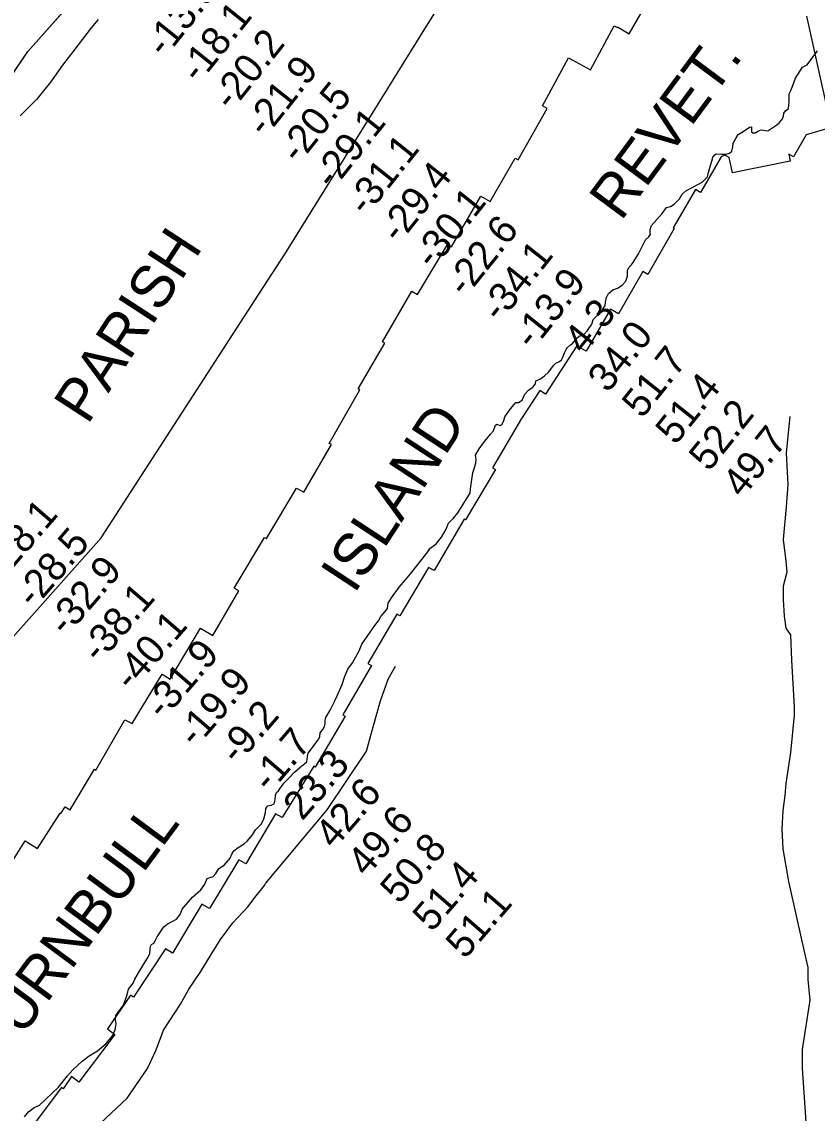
# Model space of a CAD drawing. Extents: x 3148686 to 3186545, y 916144 to 941516.
# Drawn here: x 3157131 to 3158993, y 922106 to 924661 of the extents above; entities that cross this region are included whole.
import ezdxf

# ---------------------------------------------------------------- set-up
doc = ezdxf.new("R2010")
doc.units = 0
for name, color, linetype in [('V-RIVR-EDGE', 7, 'Continuous'), ('V-RIVR-RANG', 7, 'Continuous'), ('V-RRAP-RVMT', 7, 'Continuous'), ('V-RRAP-RVMT-IDEN', 7, 'Continuous'), ('V-SITE-VEGE', 7, 'Continuous'), ('V-TOPO-BNDY', 7, 'Continuous'), ('V-TOPO-GNAM-IDEN', 7, 'Continuous'), ('V-TOPO-SHOR', 7, 'Continuous'), ('V-WETL-SWMP', 7, 'Continuous')]:
    doc.layers.add(name, color=color, linetype=linetype)

msp = doc.modelspace()

# ---------------------------------------------------------------- linework, layer by layer
at = {"layer": 'V-RIVR-EDGE'}
for points in [[(3157310.3, 924666), (3157293.6, 924646.9), (3157253, 924594.1), (3157226.7, 924559.1), (3157198.3, 924519.4), (3157165.5, 924478.7), (3157127.5, 924440.5)], [(3158912.1, 924433.6), (3158914.2, 924440), (3158915.2, 924446.7), (3158919.1, 924452.8), (3158926.2, 924458.2), (3158927.4, 924473.5), (3158927.8, 924492), (3158932.1, 924501.8), (3158942.5, 924528.8), (3158959, 924554.7), (3158970, 924559.8), (3158993.8, 924592.7)], [(3158187, 923604.9), (3158191.6, 923619.5), (3158194.4, 923628.3), (3158194.7, 923636.8), (3158193.5, 923646), (3158202.1, 923660.9), (3158211.9, 923675.2), (3158228.4, 923695.8), (3158235.7, 923703.7), (3158240.3, 923716.2), (3158243, 923718.6), (3158251.3, 923715.9), (3158255.8, 923719.2), (3158259.5, 923727.7), (3158261.7, 923736.2), (3158275.4, 923754.8), (3158287.6, 923769.4), (3158293.7, 923769.7), (3158302.3, 923774.8), (3158309, 923788.8), (3158317.5, 923798.8), (3158327.9, 923805.8), (3158334, 923813.7), (3158334.3, 923820.1), (3158338.9, 923822.2), (3158345.9, 923824.7), (3158354.8, 923832), (3158364.6, 923840.5), (3158376.5, 923857.2), (3158381.4, 923861.7), (3158389.9, 923865.4), (3158394.5, 923869.9), (3158397.8, 923875.7), (3158401.8, 923886), (3158406.7, 923894.9), (3158408.6, 923898.5), (3158415.6, 923904.3), (3158420.5, 923907.6), (3158431.4, 923921.3), (3158435.7, 923924.6), (3158447, 923928.9), (3158455.9, 923938), (3158465.9, 923952.9), (3158468.7, 923964.2), (3158489.5, 923984.2), (3158497.1, 923996.4), (3158497.4, 924004.3), (3158499.9, 924015.5), (3158504.8, 924024.7), (3158514.6, 924033.5), (3158526.1, 924037.4), (3158536.8, 924044.7), (3158545.1, 924053.8), (3158549.1, 924065.1), (3158549.1, 924072.4), (3158549.1, 924079.7), (3158553.1, 924086.7), (3158557.7, 924091.5), (3158562.2, 924097.3), (3158575.1, 924117.4), (3158591.3, 924150.8), (3158599.5, 924157.8), (3158603.2, 924162.7), (3158602.3, 924167.9), (3158602.3, 924174.6), (3158605.7, 924183.7), (3158630.1, 924212.3), (3158640.5, 924226.3), (3158650, 924228.7), (3158658.5, 924234.1), (3158670.7, 924246.6), (3158677.4, 924257.5), (3158685.7, 924264.8), (3158703.7, 924274.5), (3158723.8, 924285.4), (3158736.6, 924297.6), (3158739.1, 924309.2), (3158746.8, 924335), (3158749.8, 924346.6), (3158757.2, 924352.1), (3158769.7, 924351.1), (3158780, 924350.8), (3158788.2, 924353.2), (3158793.7, 924358.1), (3158796.2, 924367.8), (3158796.8, 924376.9), (3158803.2, 924387.6), (3158808.4, 924397), (3158817.9, 924402.8), (3158835, 924414.6), (3158839.9, 924415.2), (3158839.9, 924412.5), (3158839.8, 924403.6), (3158842.3, 924400.9), (3158848.1, 924401.2), (3158855.7, 924406), (3158862.4, 924408.1), (3158877.9, 924405.7), (3158898.7, 924419.9), (3158904.8, 924425.1), (3158912.1, 924433.6)], [(3157351.5, 922334.2), (3157359.2, 922345.4), (3157369.6, 922358.8), (3157378.1, 922383.2), (3157381.2, 922395.9), (3157391.6, 922410.2), (3157395.6, 922420), (3157406.3, 922438.5), (3157413.6, 922450.4), (3157424, 922466.5), (3157431.1, 922479), (3157432, 922490.8), (3157432.3, 922496.3), (3157434.8, 922500.9), (3157440, 922503.6), (3157443.3, 922509.7), (3157447.9, 922519.1), (3157463.5, 922542.2), (3157473.6, 922549.8), (3157484.6, 922555.6), (3157493.7, 922559.8), (3157502, 922571.4), (3157506.9, 922583.8), (3157530.7, 922611.5), (3157549.9, 922628.5), (3157559.4, 922642.2), (3157565.5, 922655.3), (3157578.9, 922660.1), (3157585.6, 922666.8), (3157592.4, 922678.7), (3157604.6, 922686.8), (3157618.6, 922703), (3157622.6, 922712.1), (3157627.2, 922720.3), (3157637.3, 922727.9), (3157651.9, 922736.7), (3157658.9, 922742.7), (3157671.1, 922757.9), (3157678.2, 922769.5), (3157692.2, 922783.5), (3157697.4, 922795), (3157701.7, 922809.9), (3157702.1, 922819.1), (3157707.2, 922825.8), (3157714.9, 922827), (3157721.9, 922830), (3157724.6, 922839.4), (3157725, 922850.1), (3157727.7, 922856.5), (3157732.3, 922860.4), (3157738.7, 922870.2), (3157745.1, 922879.3), (3157757, 922890.8), (3157769.3, 922903.9), (3157782.4, 922914.8), (3157794, 922924.2), (3157798.3, 922928.5), (3157799.8, 922941), (3157801.7, 922948.9), (3157816.6, 922968.3), (3157826.4, 922982.3), (3157828.6, 922987.8), (3157829.8, 922996.6), (3157836.2, 923004.5), (3157839.9, 923011.2), (3157841.4, 923017.3), (3157841.4, 923025.2), (3157843.3, 923031.9), (3157852.8, 923049.6), (3157865.6, 923074.5), (3157881.2, 923109.8), (3157887.1, 923129), (3157894.7, 923145.1), (3157905.4, 923160.3), (3157921, 923188), (3157927.2, 923204.1), (3157946.7, 923232.1), (3157958, 923247.3), (3157966.6, 923258.8), (3157971.5, 923268.9), (3157982.2, 923280.4), (3157987.4, 923287.4), (3157989.2, 923299.9), (3157996.3, 923312.7), (3158014.9, 923337.6), (3158029.3, 923354.3), (3158040.9, 923368.6), (3158055.8, 923387.4), (3158081.5, 923420), (3158086.7, 923427.6), (3158101, 923438.5), (3158113.9, 923454.6), (3158124.9, 923473.4), (3158129.8, 923486.8), (3158141.7, 923498.7), (3158152.1, 923511.1), (3158163.4, 923530), (3158171.9, 923544), (3158180.8, 923557.4), (3158181.8, 923567.4), (3158187, 923604.9)], [(3157137.7, 922097.5), (3157146.6, 922109), (3157160.3, 922119.3), (3157172.8, 922124.5), (3157217.4, 922166.4), (3157238.5, 922193.1), (3157250.4, 922207.1), (3157272.4, 922227.5), (3157289.2, 922239.9), (3157308.7, 922252.1), (3157328.5, 922268.8), (3157343.2, 922287.3), (3157349.9, 922301.3), (3157352.4, 922315.3), (3157350.6, 922324.4), (3157351.5, 922334.2)]]:
    msp.add_lwpolyline(points, dxfattribs=at)
at = {"layer": 'V-RRAP-RVMT'}
for p, q in [((3158553.1, 924633.1), (3158618.1, 924745.7)), ((3158968.2, 924673.8), (3159026.1, 924413.5)), ((3158462.3, 924548.7), (3158518, 924651.2)), ((3158518, 924651.2), (3158525, 924647.4)), ((3158525, 924647.4), (3158525.8, 924648.9)), ((3158525.8, 924648.9), (3158553.1, 924633.1)), ((3158350.1, 924463.8), (3158411.4, 924576.2)), ((3158411.4, 924576.2), (3158462.3, 924548.7)), ((3158293.5, 924337.9), (3158361.3, 924457.7)), ((3158361.3, 924457.7), (3158350.1, 924463.8)), ((3159026.1, 924413.5), (3158967.9, 924396.3)), ((3158967.9, 924396.3), (3158938.2, 924344.7)), ((3158777.2, 924348.6), (3158768.8, 924345)), ((3158787.1, 924343.4), (3158777.2, 924348.6)), ((3158938.2, 924344.7), (3158927.3, 924350.9)), ((3158927.3, 924350.9), (3158929.8, 924334.4)), ((3158227.9, 924240.2), (3158286.4, 924341.9)), ((3158286.4, 924341.9), (3158293.5, 924337.9)), ((3158768.8, 924345), (3158720.5, 924261.5)), ((3158794.7, 924307.4), (3158787.1, 924343.4)), ((3158929.8, 924334.4), (3158794.7, 924307.4)), ((3158137.1, 924134.4), (3158205.8, 924252.4)), ((3158205.8, 924252.4), (3158227.9, 924240.2)), ((3158708.3, 924268.5), (3158656.3, 924178.5)), ((3158720.5, 924261.5), (3158708.3, 924268.5)), ((3158658.8, 924177), (3158596.8, 924069.6)), ((3158656.3, 924178.5), (3158658.8, 924177)), ((3158057.8, 924022.8), (3158127.6, 924139.8)), ((3158127.6, 924139.8), (3158137.1, 924134.4)), ((3158585.5, 924076.1), (3158528.5, 923977.4)), ((3158596.8, 924069.6), (3158585.5, 924076.1)), ((3157975.4, 923912), (3158044.3, 924030.4)), ((3158044.3, 924030.4), (3158057.8, 924022.8)), ((3158509.4, 923988.4), (3158452.5, 923889.6)), ((3158528.5, 923977.4), (3158509.4, 923988.4)), ((3157919, 923801.3), (3157981.2, 923908.6)), ((3157981.2, 923908.6), (3157975.4, 923912)), ((3158430.8, 923902.2), (3158357.6, 923789.3)), ((3158452.5, 923889.6), (3158430.8, 923902.2)), ((3157850.8, 923674), (3157922.7, 923799.2)), ((3157922.7, 923799.2), (3157919, 923801.3)), ((3158343.9, 923798.1), (3158301.1, 923732.3)), ((3158357.6, 923789.3), (3158343.9, 923798.1)), ((3158301.1, 923732.3), (3158233.3, 923616.9)), ((3157791.2, 923560), (3157856, 923671.1)), ((3157856, 923671.1), (3157850.8, 923674)), ((3158240.4, 923612.7), (3158170.2, 923494.8)), ((3158233.3, 923616.9), (3158240.4, 923612.7)), ((3157703.9, 923451.1), (3157774.6, 923569)), ((3157774.6, 923569), (3157791.2, 923560)), ((3158166.6, 923496.8), (3158096.4, 923376.3)), ((3158170.2, 923494.8), (3158166.6, 923496.8)), ((3157628.5, 923334.7), (3157699.2, 923453.9)), ((3157699.2, 923453.9), (3157703.9, 923451.1)), ((3158083.3, 923383.6), (3158015.9, 923270.4)), ((3158096.4, 923376.3), (3158083.3, 923383.6)), ((3157578.5, 923224.4), (3157639.5, 923328.5)), ((3157639.5, 923328.5), (3157628.5, 923334.7)), ((3158009.5, 923274), (3157941.5, 923158.4)), ((3158015.9, 923270.4), (3158009.5, 923274)), ((3157478.8, 923122.3), (3157549.5, 923241.2)), ((3157549.5, 923241.2), (3157578.5, 923224.4)), ((3157949.5, 923153.6), (3157882.7, 923038.1)), ((3157941.5, 923158.4), (3157949.5, 923153.6)), ((3157389.3, 923017.9), (3157459.4, 923133.7)), ((3157459.4, 923133.7), (3157478.8, 923122.3)), ((3157304.3, 922909.2), (3157372.2, 923027.1)), ((3157372.2, 923027.1), (3157389.3, 923017.9)), ((3157887.9, 923035.1), (3157817.8, 922916.3)), ((3157882.7, 923038.1), (3157887.9, 923035.1)), ((3157814.6, 922918), (3157740.8, 922797.9)), ((3157817.8, 922916.3), (3157814.6, 922918)), ((3157244.3, 922816), (3157301.2, 922910.9)), ((3157301.2, 922910.9), (3157304.3, 922909.2)), ((3157222.8, 922807.5), (3157232.6, 922823.3)), ((3157232.6, 922823.3), (3157244.3, 922816)), ((3157168.1, 922725.5), (3157220.6, 922808.6)), ((3157220.6, 922808.6), (3157222.8, 922807.5)), ((3157725.4, 922806.7), (3157655.8, 922689.7)), ((3157740.8, 922797.9), (3157725.4, 922806.7)), ((3157084.6, 922656.1), (3157139.3, 922743.6)), ((3157139.3, 922743.6), (3157168.1, 922725.5)), ((3157639.1, 922699.1), (3157570.2, 922585.1)), ((3157655.8, 922689.7), (3157639.1, 922699.1)), ((3157552.4, 922594.9), (3157484.3, 922480.2)), ((3157570.2, 922585.1), (3157552.4, 922594.9)), ((3157467.4, 922490.9), (3157392.5, 922377.2)), ((3157484.3, 922480.2), (3157467.4, 922490.9)), ((3157385.5, 922381.8), (3157331.7, 922303.1)), ((3157392.5, 922377.2), (3157385.5, 922381.8)), ((3157348.7, 922290.2), (3157264.4, 922178.6)), ((3157331.7, 922303.1), (3157348.7, 922290.2)), ((3157247.1, 922191.5), (3157227.7, 922163.1)), ((3157264.4, 922178.6), (3157247.1, 922191.5)), ((3157223.9, 922165.7), (3157164.6, 922087)), ((3157227.7, 922163.1), (3157223.9, 922165.7))]:
    msp.add_line(p, q, dxfattribs=at)
at = {"layer": 'V-SITE-VEGE'}
for p, q in [((3157145.2, 924591), (3157261.8, 924722.8)), ((3157064.5, 924472.8), (3157145.2, 924591))]:
    msp.add_line(p, q, dxfattribs=at)
at = {"layer": 'V-TOPO-BNDY'}
msp.add_lwpolyline([(3156122.4, 922098.2), (3156168.8, 922145.8), (3156428.7, 922411), (3156852.6, 922931.2), (3157254.5, 923382.8), (3157305.3, 923439.5), (3157317.3, 923453.1), (3157677.4, 924009.7), (3157746.6, 924116.6), (3157949.7, 924442.8), (3158078.5, 924650.3), (3158117.2, 924712.4), (3158363.3, 925108.2), (3158430.5, 925235.2), (3158537.2, 925435.5), (3158721.6, 925781.3), (3158837.1, 925997.9), (3159006.2, 926311.1), (3159280.9, 926819.7)], dxfattribs=at)
at = {"layer": 'V-TOPO-SHOR'}
for points in [[(3158929.4, 923737.2), (3158920.5, 923652), (3158924.8, 923577.6), (3158920.4, 923525.2), (3158913.8, 923448.7), (3158920.3, 923398.4), (3158922.4, 923372.1), (3158913.6, 923339.3), (3158913.6, 923308.7), (3158915.7, 923269.4), (3158920.1, 923241), (3158931, 923225.6), (3158933.1, 923166.6), (3158939.6, 923057.3), (3158939.6, 923037.6), (3158930.7, 922950.2), (3158919.7, 922878), (3158917.5, 922849.6), (3158913.1, 922814.6), (3158910.9, 922770.9), (3158913, 922725), (3158926, 922648.5), (3158945.6, 922561), (3158963, 922484.5), (3158971.7, 922447.3), (3158971.7, 922418.9), (3158976, 922370.8), (3158958.4, 922254.9), (3158958.4, 922211.2), (3158973.4, 921981.6)], [(3157191.6, 921966), (3157377.6, 922140.7), (3157425.8, 922210.6), (3157445.5, 922254.3), (3157463, 922300.2), (3157502.5, 922361.4), (3157522.2, 922396.3), (3157550.6, 922437.8), (3157574.7, 922477.2), (3157596.6, 922512.1), (3157625.1, 922551.5), (3157660.1, 922588.6), (3157679.8, 922614.8), (3157699.5, 922638.8), (3157701.7, 922643.2), (3157846.2, 922815.8), (3157938.1, 922953.4), (3157953.5, 923010.2), (3157971.1, 923071.4), (3157988.6, 923121.7), (3158006.1, 923152.3)]]:
    msp.add_lwpolyline(points, dxfattribs=at)
at = {"layer": 'V-WETL-SWMP'}
msp.add_lwpolyline([(3157064.5, 924472.8), (3157145.2, 924591), (3157261.8, 924722.8)], dxfattribs=at)

# ---------------------------------------------------------------- texts
at = {"layer": 'V-RIVR-RANG'}
for s, rotation, p in [('-13.9', 51.4283, (3157465.8, 924574.1)), ('-18.1', 51.4283, (3157545.8, 924514)), ('-20.2', 51.4283, (3157622.6, 924449.9)), ('-21.9', 51.4283, (3157700.8, 924387.6)), ('-20.5', 51.4283, (3157779.3, 924325.6)), ('-29.1', 51.4283, (3157859.1, 924265.3)), ('-31.1', 51.4283, (3157937.4, 924203.2)), ('-29.4', 51.4283, (3158014.3, 924139.1)), ('-30.1', 51.4283, (3158094.1, 924078.8)), ('-22.6', 51.4283, (3158169.8, 924013.4)), ('-34.1', 51.4283, (3158250.8, 923954.5)), ('-13.9', 51.4283, (3158327.5, 923890.3)), ('4.3', 51.4283, (3158447.4, 923880.3)), ('34.0', 51.4283, (3158503.2, 923789.9)), ('51.7', 51.4283, (3158583.3, 923730)), ('51.4', 51.4283, (3158661.7, 923667.8)), ('52.2', 51.4283, (3158740, 923605.7)), ('49.7', 51.4283, (3158818.3, 923543.5)), ('-28.1', 49.1683, (3157085.2, 923351.9)), ('-28.5', 49.1683, (3157159.5, 923284.9)), ('-32.9', 49.1683, (3157235.1, 923219.5)), ('-38.1', 49.1683, (3157312.7, 923156.3)), ('-40.1', 49.1683, (3157388.5, 923091.1)), ('-31.9', 49.1683, (3157462.6, 923023.9)), ('-19.9', 49.1683, (3157538.4, 922958.7)), ('-9.2', 49.1683, (3157636.1, 922918.9)), ('-1.7', 49.1683, (3157712, 922853.7)), ('23.3', 49.1683, (3157787.8, 922788.5)), ('42.6', 49.1683, (3157862.4, 922721.9)), ('49.6', 49.1683, (3157938.2, 922656.7)), ('50.8', 49.1683, (3158015.3, 922592.9)), ('51.4', 49.1683, (3158091.1, 922527.7)), ('51.1', 49.1683, (3158168.5, 922464.3))]:
    msp.add_text(s, height=67, rotation=rotation, dxfattribs=at).set_placement(p)
at = {"layer": 'V-RRAP-RVMT-IDEN'}
for s, rotation, p in [('REVET.', 53.4608, (3158533.9, 924192.2)), ('ISLAND', 56.6929, (3157909.4, 923319.6)), ('TURNBULL', 53.4608, (3157083, 922218.1))]:
    msp.add_text(s, height=100, rotation=rotation, dxfattribs=at).set_placement(p)
at = {"layer": 'V-TOPO-GNAM-IDEN'}
msp.add_text('PARISH', height=100, rotation=57.0062, dxfattribs=at).set_placement((3157285.2, 923715.6))

doc.saveas('drawing.dxf')
